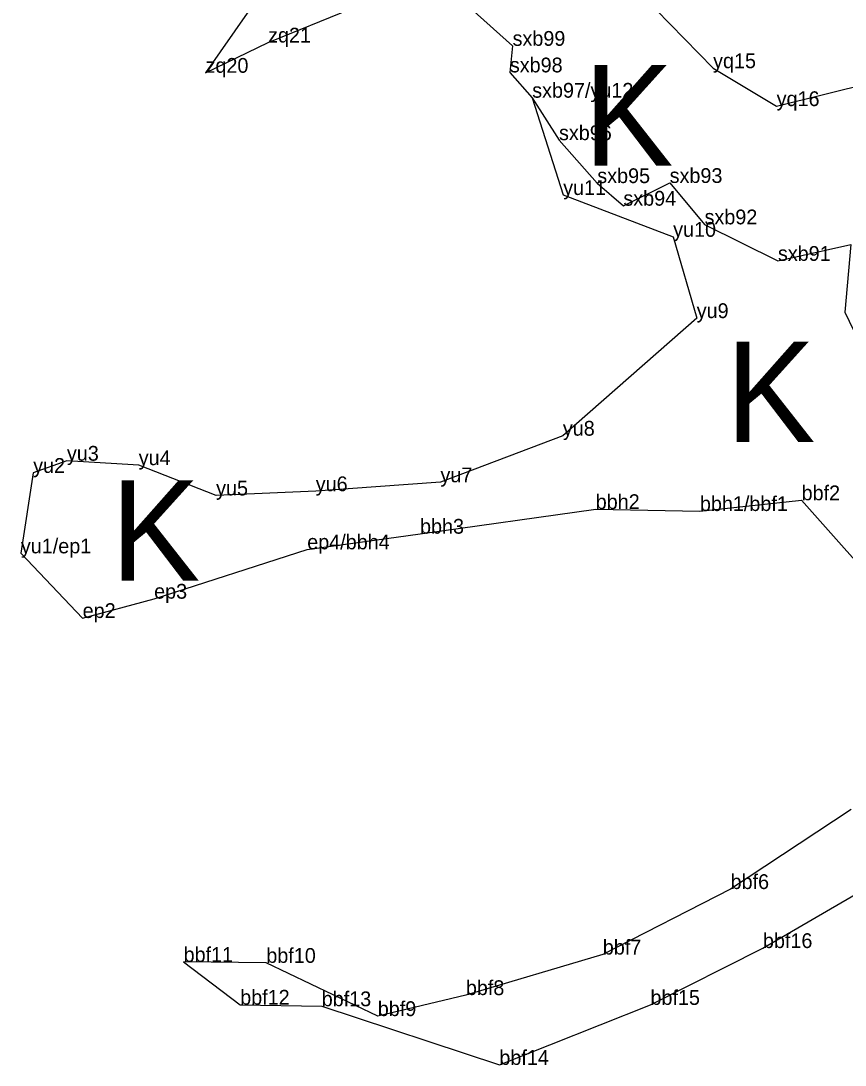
# Model space of a CAD drawing. Extents: x 2072529 to 2268812, y 436423 to 470008.
# Drawn here: x 2246748.4 to 2247027.1, y 439648.8 to 440002.1 of the extents above; entities that cross this region are included whole.
import ezdxf

# ---------------------------------------------------------------- set-up
doc = ezdxf.new("R2010")
doc.units = 0
for name, color, linetype in [('Old_Level_10', 7, 'Continuous'), ('Old_Level_20', 7, 'Continuous'), ('Old_Level_52', 7, 'Continuous'), ('Old_Level_55', 7, 'Continuous'), ('Old_Level_60', 7, 'Continuous')]:
    doc.layers.add(name, color=color, linetype=linetype)

msp = doc.modelspace()

# ---------------------------------------------------------------- linework, layer by layer
at = {"layer": 'Old_Level_10'}
msp.add_lwpolyline([(2246886.695, 440018.818), (2246914.629, 439993.645), (2246913.702, 439984.658), (2246921.262, 439976.089), (2246930.332, 439961.735), (2246943.283, 439947.201), (2246952.098, 439939.558), (2246967.748, 439947.252), (2246979.542, 439933.252), (2247004.359, 439920.906), (2247029.039, 439926.419), (2247026.981, 439903.545), (2247040.045, 439876.322)], dxfattribs=at)
at = {"layer": 'Old_Level_20'}
for p, q in [((2246831.956, 439994.756), (2246831.956, 439994.756)), ((2246914.629, 439993.645), (2246914.629, 439993.645)), ((2246982.432, 439986.074), (2246982.432, 439986.074)), ((2246810.798, 439984.516), (2246810.798, 439984.516)), ((2246913.702, 439984.658), (2246913.702, 439984.658)), ((2246921.262, 439976.089), (2246921.262, 439976.089)), ((2246921.262, 439976.089), (2246921.262, 439976.089)), ((2246921.262, 439976.089), (2246921.262, 439976.089)), ((2247003.925, 439973.249), (2247003.925, 439973.249)), ((2246930.332, 439961.735), (2246930.332, 439961.735)), ((2246943.283, 439947.201), (2246943.283, 439947.201)), ((2246967.748, 439947.252), (2246967.748, 439947.252)), ((2246931.746, 439943.182), (2246931.746, 439943.182)), ((2246931.746, 439943.182), (2246931.746, 439943.182)), ((2246952.098, 439939.558), (2246952.098, 439939.558)), ((2246979.542, 439933.252), (2246979.542, 439933.252)), ((2246968.931, 439929.035), (2246968.931, 439929.035)), ((2246968.931, 439929.035), (2246968.931, 439929.035)), ((2247004.359, 439920.906), (2247004.359, 439920.906)), ((2246976.892, 439901.538), (2246976.892, 439901.538)), ((2246976.892, 439901.538), (2246976.892, 439901.538)), ((2247026.981, 439903.545), (2247026.981, 439903.545)), ((2246931.63, 439861.756), (2246931.63, 439861.756)), ((2246931.63, 439861.756), (2246931.63, 439861.756)), ((2246763.922, 439853.292), (2246763.922, 439853.292)), ((2246763.922, 439853.292), (2246763.922, 439853.292)), ((2246788.2, 439851.785), (2246788.2, 439851.785)), ((2246788.2, 439851.785), (2246788.2, 439851.785)), ((2246752.512, 439849.179), (2246752.512, 439849.179)), ((2246752.512, 439849.179), (2246752.512, 439849.179)), ((2246890.236, 439845.992), (2246890.236, 439845.992)), ((2246890.236, 439845.992), (2246890.236, 439845.992)), ((2246814.37, 439841.547), (2246814.37, 439841.547)), ((2246814.37, 439841.547), (2246814.37, 439841.547)), ((2246848.061, 439842.981), (2246848.061, 439842.981)), ((2246848.061, 439842.981), (2246848.061, 439842.981)), ((2247012.36, 439839.915), (2247012.36, 439839.915)), ((2246942.742, 439836.931), (2246942.742, 439836.931)), ((2246977.965, 439836.269), (2246977.965, 439836.269)), ((2246883.332, 439828.605), (2246883.332, 439828.605)), ((2246845.189, 439823.311), (2246845.189, 439823.311)), ((2246748.356, 439821.96), (2246748.356, 439821.96)), ((2246748.356, 439821.96), (2246748.356, 439821.96)), ((2246793.412, 439806.617), (2246793.412, 439806.617)), ((2246769.243, 439800.082), (2246769.243, 439800.082)), ((2246769.243, 439800.082), (2246769.243, 439800.082)), ((2246988.346, 439708.395), (2246988.346, 439708.395)), ((2246945.137, 439686.241), (2246945.137, 439686.241)), ((2246999.286, 439688.436), (2246999.286, 439688.436)), ((2246803.377, 439683.745), (2246803.377, 439683.745)), ((2246831.345, 439683.425), (2246831.345, 439683.425)), ((2246898.826, 439672.517), (2246898.826, 439672.517)), ((2246822.513, 439669.276), (2246822.513, 439669.276)), ((2246850.088, 439668.749), (2246850.088, 439668.749)), ((2246961.256, 439669.204), (2246961.256, 439669.204)), ((2246869.049, 439665.418), (2246869.049, 439665.418)), ((2246910.162, 439648.903), (2246910.162, 439648.903))]:
    msp.add_line(p, q, dxfattribs=at)
at = {"layer": 'Old_Level_52'}
for points in [[(2246928.79, 440355.336), (2246931.306, 440332.4), (2246935.051, 440314.949), (2246940.745, 440293.863), (2246926.257, 440257.883), (2246916.225, 440247.225), (2246931.306, 440228.038), (2246924.176, 440213.876), (2246896.438, 440200.883), (2246884.695, 440182.531), (2246883.238, 440156.21), (2246883.317, 440139.166), (2246867.49, 440116.152), (2246850.966, 440089.203), (2246826.478, 440075.713), (2246830.299, 440069.984), (2246848.821, 440052.158), (2246844.798, 440030.558), (2246825.697, 440005.834), (2246810.798, 439984.516), (2246831.956, 439994.756), (2246860.23, 440006.28), (2246886.695, 440018.818)], [(2246958.274, 440011.001), (2246982.432, 439986.074), (2247003.925, 439973.249), (2247036.067, 439981.256)], [(2246921.262, 439976.089), (2246931.746, 439943.182), (2246968.931, 439929.035), (2246976.892, 439901.538), (2246931.63, 439861.756), (2246890.236, 439845.992), (2246848.061, 439842.981), (2246814.37, 439841.547), (2246788.2, 439851.785), (2246763.922, 439853.292), (2246752.512, 439849.179), (2246748.356, 439821.96), (2246769.243, 439800.082), (2246793.412, 439806.617), (2246845.189, 439823.311), (2246883.332, 439828.605), (2246942.742, 439836.931), (2246977.965, 439836.269), (2247012.36, 439839.915), (2247043.137, 439805.319)], [(2247029.083, 439735.301), (2246988.346, 439708.395), (2246945.137, 439686.241), (2246898.826, 439672.517), (2246869.049, 439665.418), (2246831.345, 439683.425), (2246803.377, 439683.745), (2246822.513, 439669.276), (2246850.088, 439668.749), (2246910.162, 439648.903), (2246961.256, 439669.204), (2246999.286, 439688.436), (2247037.506, 439710.572)]]:
    msp.add_lwpolyline(points, dxfattribs=at)

# ---------------------------------------------------------------- texts
at = {"layer": 'Old_Level_55'}
for p in [(2246938.65, 439953.12), (2246986.726, 439859.568), (2246778.675, 439812.709)]:
    msp.add_text('K', height=34, dxfattribs=at).set_placement(p)
at = {"layer": 'Old_Level_60'}
for s, p in [('zq21', (2246831.956, 439994.756)), ('sxb99', (2246914.629, 439993.645)), ('zq20', (2246810.798, 439984.516)), ('sxb98', (2246913.702, 439984.658)), ('yq15', (2246982.432, 439986.074)), ('sxb97/yu12', (2246921.262, 439976.089)), ('sxb97/yu12', (2246921.262, 439976.089)), ('sxb97/yu12', (2246921.262, 439976.089)), ('yq16', (2247003.925, 439973.249)), ('sxb96', (2246930.332, 439961.735)), ('sxb95', (2246943.283, 439947.201)), ('sxb93', (2246967.748, 439947.252)), ('yu11', (2246931.746, 439943.182)), ('yu11', (2246931.746, 439943.182)), ('sxb94', (2246952.098, 439939.558)), ('sxb92', (2246979.542, 439933.252)), ('yu10', (2246968.931, 439929.035)), ('yu10', (2246968.931, 439929.035)), ('sxb91', (2247004.359, 439920.906)), ('yu9', (2246976.892, 439901.538)), ('yu9', (2246976.892, 439901.538)), ('yu8', (2246931.63, 439861.756)), ('yu8', (2246931.63, 439861.756)), ('yu3', (2246763.922, 439853.292)), ('yu3', (2246763.922, 439853.292)), ('yu4', (2246788.2, 439851.785)), ('yu4', (2246788.2, 439851.785)), ('yu2', (2246752.512, 439849.179)), ('yu2', (2246752.512, 439849.179)), ('yu6', (2246848.061, 439842.981)), ('yu6', (2246848.061, 439842.981)), ('yu7', (2246890.236, 439845.992)), ('yu7', (2246890.236, 439845.992)), ('yu5', (2246814.37, 439841.547)), ('yu5', (2246814.37, 439841.547)), ('bbf2', (2247012.36, 439839.915)), ('bbh2', (2246942.742, 439836.931)), ('bbh1/bbf1', (2246977.965, 439836.269)), ('bbh3', (2246883.332, 439828.605)), ('yu1/ep1', (2246748.356, 439821.96)), ('yu1/ep1', (2246748.356, 439821.96)), ('ep4/bbh4', (2246845.189, 439823.311)), ('ep3', (2246793.412, 439806.617)), ('ep2', (2246769.243, 439800.082)), ('ep2', (2246769.243, 439800.082)), ('bbf6', (2246988.346, 439708.395)), ('bbf16', (2246999.286, 439688.436)), ('bbf7', (2246945.137, 439686.241)), ('bbf11', (2246803.377, 439683.745)), ('bbf10', (2246831.345, 439683.425)), ('bbf8', (2246898.826, 439672.517)), ('bbf12', (2246822.513, 439669.276)), ('bbf13', (2246850.088, 439668.749)), ('bbf15', (2246961.256, 439669.204)), ('bbf9', (2246869.049, 439665.418)), ('bbf14', (2246910.162, 439648.903))]:
    msp.add_text(s, height=5, dxfattribs=at).set_placement(p)

doc.saveas('drawing.dxf')
